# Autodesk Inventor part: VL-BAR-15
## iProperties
Created: 2005-08
Part Number: VL-BAR-15
Document SubType Name: Sheet Metal
Density: 1 g/cm^3
Mass: 2.5361 g
Surface Area: 49.0883 cm^2
Volume: 2.5361 cm^3
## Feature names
1. Rectangular Pattern1
2. Plate1
